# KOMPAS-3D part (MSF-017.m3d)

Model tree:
1. Ось X
2. Ось Y
3. Ось Z
4. Начало координат  (labels: Операция без истории:1)

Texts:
  Линия-выноска #1
  Линия-выноска #2
  Линия-выноска #3
  Отклонения формы и база
  Марка координационной оси
  Марка/позиционное обозначение с линией-выноской
  Марка/позиционное обозначение на линии
  Марка/позиционное обозначение без линии-выноски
